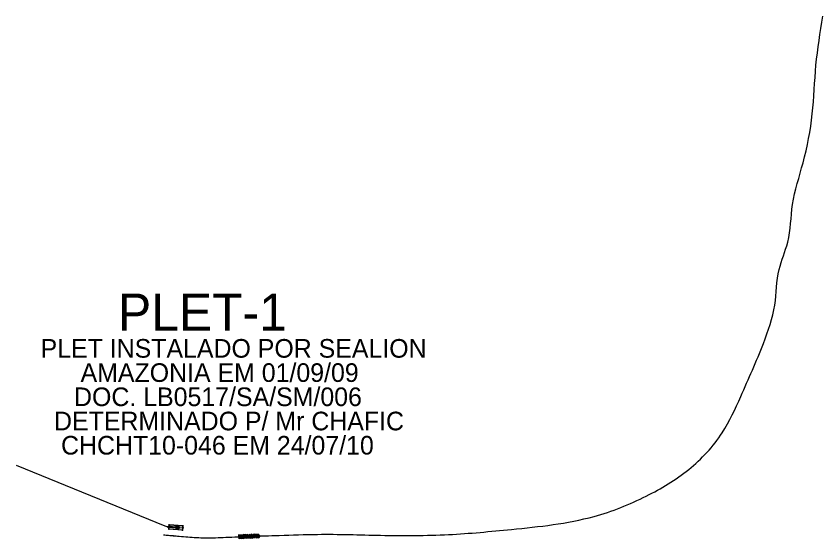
# Model space of a CAD drawing. Extents: x 387828 to 391861, y 7650362 to 7652502.
# Drawn here: x 387828.2 to 387996.5, y 7651913.7 to 7652022.6 of the extents above; entities that cross this region are included whole.
import ezdxf

# ---------------------------------------------------------------- set-up
doc = ezdxf.new("R2010")
doc.units = 0
for name, color, linetype in [('Duto rigido de gas', 7, 'Continuous'), ('Dutos flexiveis', 7, 'Continuous'), ('PLET', 7, 'Continuous'), ('Sinalizacao', 7, 'Continuous'), ('Texto dos PLETs', 7, 'Continuous')]:
    doc.layers.add(name, color=color, linetype=linetype)

msp = doc.modelspace()

# ---------------------------------------------------------------- linework, layer by layer
at = {"layer": 'Duto rigido de gas'}
for p, q in [((387828.2337940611, 7651929.046525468), (387859.23233954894, 7651916.408942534)), ((387859.23233954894, 7651916.408942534), (387859.8424600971, 7651916.225313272))]:
    msp.add_line(p, q, dxfattribs=at)
at = {"layer": 'Dutos flexiveis'}
msp.add_spline([(387858.9639002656, 7651914.554573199), (387860.02357707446, 7651914.452215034), (387860.5534153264, 7651914.401036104), (387860.81833460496, 7651914.375446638), (387860.9507940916, 7651914.362652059), (387861.01702414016, 7651914.356254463), (387861.05013885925, 7651914.353055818), (387860.9847517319, 7651914.3515268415), (387860.98296060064, 7651914.350719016), (387861.01652729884, 7651914.35029603), (387861.0832538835, 7651914.349857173), (387862.2169856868, 7651914.24647084), (387864.03775597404, 7651914.096212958), (387867.70359752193, 7651913.928216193), (387871.95911862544, 7651914.028037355), (387877.05618549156, 7651914.246396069), (387883.09038117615, 7651914.429401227), (387891.08610614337, 7651914.64568041), (387904.23386455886, 7651914.449102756), (387918.42349711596, 7651914.598061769), (387931.49733237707, 7651915.6772432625), (387948.75605853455, 7651918.3780944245), (387959.6423175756, 7651922.619168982), (387968.4754893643, 7651928.1755973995), (387975.46898586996, 7651935.817784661), (387979.33777703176, 7651943.390627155), (387984.05923062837, 7651954.438197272), (387986.4251881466, 7651962.435941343), (387987.32789361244, 7651969.835424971), (387989.11497970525, 7651975.517289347), (387990.140892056, 7651983.368984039), (387992.3269374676, 7651992.079284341), (387994.2400915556, 7652002.24609241), (387995.02, 7652012.41), (387996.45363353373, 7652022.634781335)], degree=3, dxfattribs=at)
at = {"layer": 'PLET'}
for p, q in [((387863.2342316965, 7651915.959320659), (387859.8436695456, 7651916.212476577)), ((387860.0033716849, 7651916.135371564), (387859.94703512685, 7651916.119522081)), ((387860.01379589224, 7651916.274982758), (387859.9604376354, 7651916.299022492)), ((387863.0097640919, 7651915.504772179), (387860.00313303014, 7651915.729262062)), ((387860.07312326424, 7651916.66665273), (387863.07975432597, 7651916.442162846)), ((387860.09079592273, 7651915.627452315), (387860.17493301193, 7651916.754315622)), ((387860.2776082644, 7651916.114895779), (387860.33096652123, 7651916.090856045)), ((387860.28803247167, 7651916.254506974), (387860.34436902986, 7651916.270356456)), ((387860.5558607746, 7651916.013897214), (387860.57819788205, 7651916.313064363)), ((387860.8410400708, 7651916.072826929), (387860.78470351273, 7651916.056977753)), ((387860.8514642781, 7651916.212438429), (387860.7981060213, 7651916.236478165)), ((387860.8514642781, 7651916.212438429), (387860.8410400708, 7651916.072826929)), ((387860.8410400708, 7651916.072826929), (387861.53411084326, 7651916.021079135)), ((387861.5395489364, 7651916.161062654), (387860.8514642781, 7651916.212438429)), ((387861.9196237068, 7651916.48365856), (387861.8570790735, 7651915.645990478)), ((387862.9920914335, 7651916.543972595), (387862.9079543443, 7651915.417109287))]:
    msp.add_line(p, q, dxfattribs=at)
for points in [[(387859.9440568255, 7651916.079633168), (387859.8941956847, 7651916.083356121), (387859.91392712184, 7651916.347620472), (387859.9637882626, 7651916.34389752)], [(387860.2776082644, 7651916.114895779), (387860.0033716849, 7651916.135371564), (387860.01379589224, 7651916.274982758), (387860.28803247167, 7651916.254506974)], [(387860.3287328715, 7651916.0609393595), (387860.358649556, 7651916.058705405), (387860.37651936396, 7651916.298039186), (387860.3466026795, 7651916.300273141)], [(387860.782469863, 7651916.0270610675), (387860.7525531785, 7651916.029294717), (387860.77042298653, 7651916.268628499), (387860.800339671, 7651916.266394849)]]:
    msp.add_lwpolyline(points, close=True, dxfattribs=at)
for points in [[(387860.0762895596, 7651915.768925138), (387860.13957853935, 7651916.616565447)], [(387860.1261507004, 7651915.765202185), (387860.18943968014, 7651916.612842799)], [(387862.86829126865, 7651915.490265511), (387860.1408832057, 7651915.693907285)], [(387862.8720142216, 7651915.540126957), (387860.1446058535, 7651915.743768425)], [(387860.2108731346, 7651916.6312979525), (387862.93828150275, 7651916.427656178)], [(387860.2145960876, 7651916.681159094), (387862.94200415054, 7651916.477517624)], [(387860.47676046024, 7651916.230387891), (387860.38649159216, 7651916.29729484), (387860.3686217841, 7651916.057961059), (387860.46321176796, 7651916.116079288)], [(387860.6612469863, 7651916.216613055), (387860.76045075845, 7651916.26937315), (387860.7425809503, 7651916.030039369), (387860.65767052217, 7651916.1015601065)], [(387862.9567366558, 7651916.406222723), (387862.89344767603, 7651915.55858211)], [(387863.0065977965, 7651916.402499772), (387862.94330881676, 7651915.554859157)]]:
    msp.add_lwpolyline(points, dxfattribs=at)
for centre, radius in [((387860.0991326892, 7651915.722053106), 0.05080000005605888), ((387860.0991326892, 7651915.722053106), 0.0410957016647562), ((387860.16912288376, 7651916.659443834), 0.050800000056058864), ((387860.16912288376, 7651916.659443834), 0.0410957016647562), ((387861.8891957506, 7651916.065658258), 0.360000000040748), ((387861.8891957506, 7651916.065658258), 0.34354766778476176), ((387861.8891957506, 7651916.065658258), 0.24253865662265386), ((387861.8891957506, 7651916.065658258), 0.17564168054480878), ((387861.8891957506, 7651916.065658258), 0.15700318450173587), ((387861.8891957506, 7651916.065658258), 0.13946325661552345), ((387861.8891957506, 7651916.065658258), 0.11884864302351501), ((387861.8891957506, 7651916.065658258), 0.09656603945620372), ((387861.88748714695, 7651916.066108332), 0.06499999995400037), ((387862.9162909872, 7651915.511710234), 0.05080000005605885), ((387862.9162909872, 7651915.511710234), 0.0410957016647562), ((387862.98628118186, 7651916.449100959), 0.05080000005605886), ((387862.98628118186, 7651916.449100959), 0.0410957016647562)]:
    msp.add_circle(centre, radius, dxfattribs=at)
for major_axis, ratio in [((-0.007641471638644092, -0.1108675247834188), 0.997054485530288), ((-0.0014263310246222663, -0.02069415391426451), 0.9970544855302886)]:
    msp.add_ellipse((387860.5664856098, 7651916.164437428), major_axis=major_axis, ratio=ratio, dxfattribs=at)
at = {"layer": 'Sinalizacao'}
for p, q in [((387874.70777520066, 7651913.703699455), (387874.6737040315, 7651914.628071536)), ((387874.6737040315, 7651914.628071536), (387874.6907394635, 7651914.165885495)), ((387874.6737040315, 7651914.628071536), (387874.6907394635, 7651914.165885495)), ((387874.6737040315, 7651914.628071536), (387875.13293923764, 7651914.1821845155)), ((387875.13293923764, 7651914.1821845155), (387874.70777520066, 7651913.703699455)), ((387875.14997497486, 7651913.719998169), (387875.11590380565, 7651914.644370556)), ((387875.11590380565, 7651914.644370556), (387875.13293923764, 7651914.1821845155)), ((387875.11590380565, 7651914.644370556), (387875.13293923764, 7651914.1821845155)), ((387875.11590380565, 7651914.644370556), (387875.57513901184, 7651914.19848323)), ((387875.57513901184, 7651914.19848323), (387875.14997497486, 7651913.719998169)), ((387875.592174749, 7651913.736297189), (387875.5581035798, 7651914.660669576)), ((387875.5581035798, 7651914.660669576), (387875.57513901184, 7651914.19848323)), ((387875.5581035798, 7651914.660669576), (387875.57513901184, 7651914.19848323)), ((387875.5581035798, 7651914.660669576), (387876.017338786, 7651914.21478225)), ((387876.017338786, 7651914.21478225), (387875.592174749, 7651913.736297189)), ((387876.03437421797, 7651913.752596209), (387876.0003030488, 7651914.676968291)), ((387876.0003030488, 7651914.676968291), (387876.017338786, 7651914.21478225)), ((387876.0003030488, 7651914.676968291), (387876.017338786, 7651914.21478225)), ((387876.0003030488, 7651914.676968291), (387876.4595385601, 7651914.231081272)), ((387876.4595385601, 7651914.231081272), (387876.03437421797, 7651913.752596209)), ((387876.4765739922, 7651913.768894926), (387876.44250282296, 7651914.693267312)), ((387876.44250282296, 7651914.693267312), (387876.4595385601, 7651914.231081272)), ((387876.44250282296, 7651914.693267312), (387876.4595385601, 7651914.231081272)), ((387876.44250282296, 7651914.693267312), (387876.90173833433, 7651914.247379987)), ((387876.90173833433, 7651914.247379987), (387876.4765739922, 7651913.768894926)), ((387876.9324988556, 7651913.777820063), (387876.8955223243, 7651914.702080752)), ((387876.8955223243, 7651914.702080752), (387876.91401074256, 7651914.23995056)), ((387876.8955223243, 7651914.702080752), (387876.91401074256, 7651914.23995056)), ((387876.8955223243, 7651914.702080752), (387877.35615680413, 7651914.257639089)), ((387877.35615680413, 7651914.257639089), (387876.9324988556, 7651913.777820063)), ((387877.3746452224, 7651913.795508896), (387877.33766869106, 7651914.719769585)), ((387877.33766869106, 7651914.719769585), (387877.35615680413, 7651914.257639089)), ((387877.33766869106, 7651914.719769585), (387877.35615680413, 7651914.257639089)), ((387877.33766869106, 7651914.719769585), (387877.7983031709, 7651914.275327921)), ((387877.7983031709, 7651914.275327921), (387877.3746452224, 7651913.795508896)), ((387877.81679158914, 7651913.81319773), (387877.7798150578, 7651914.737458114)), ((387877.7798150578, 7651914.737458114), (387877.7983031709, 7651914.275327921)), ((387877.7798150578, 7651914.737458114), (387877.7983031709, 7651914.275327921)), ((387877.7798150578, 7651914.737458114), (387878.24044953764, 7651914.293016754)), ((387878.24044953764, 7651914.293016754), (387877.81679158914, 7651913.81319773)), ((387878.2589376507, 7651913.830886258), (387878.22196142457, 7651914.755146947)), ((387878.22196142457, 7651914.755146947), (387878.24044953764, 7651914.293016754)), ((387878.22196142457, 7651914.755146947), (387878.24044953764, 7651914.293016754)), ((387878.22196142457, 7651914.755146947), (387878.6825959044, 7651914.310705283)), ((387878.6825959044, 7651914.310705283), (387878.2589376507, 7651913.830886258)), ((387878.70108401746, 7651913.848575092), (387878.66410748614, 7651914.772835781)), ((387878.66410748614, 7651914.772835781), (387878.6825959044, 7651914.310705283)), ((387878.66410748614, 7651914.772835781), (387878.6825959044, 7651914.310705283)), ((387878.66410748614, 7651914.772835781), (387879.12474227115, 7651914.328394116)), ((387879.12474227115, 7651914.328394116), (387878.70108401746, 7651913.848575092))]:
    msp.add_line(p, q, dxfattribs=at)

# ---------------------------------------------------------------- texts
at = {"layer": 'Texto dos PLETs'}
for s, height, p in [('PLET-1', 7.76448, (387849.48, 7651957.0600000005)), ('PLET INSTALADO POR SEALION ', 3.88224, (387833.33, 7651951.46)), ('AMAZONIA EM 01/09/09', 3.88224, (387841.67, 7651946.41)), ('DOC. LB0517/SA/SM/006', 3.88224, (387840.31, 7651941.37)), ('DETERMINADO P/ Mr CHAFIC', 3.88224, (387836.14, 7651936.32)), ('CHCHT10-046 EM 24/07/10', 3.88224, (387837.60000000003, 7651931.2700000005))]:
    msp.add_text(s, height=height, dxfattribs=at).set_placement(p)

doc.saveas('drawing.dxf')
